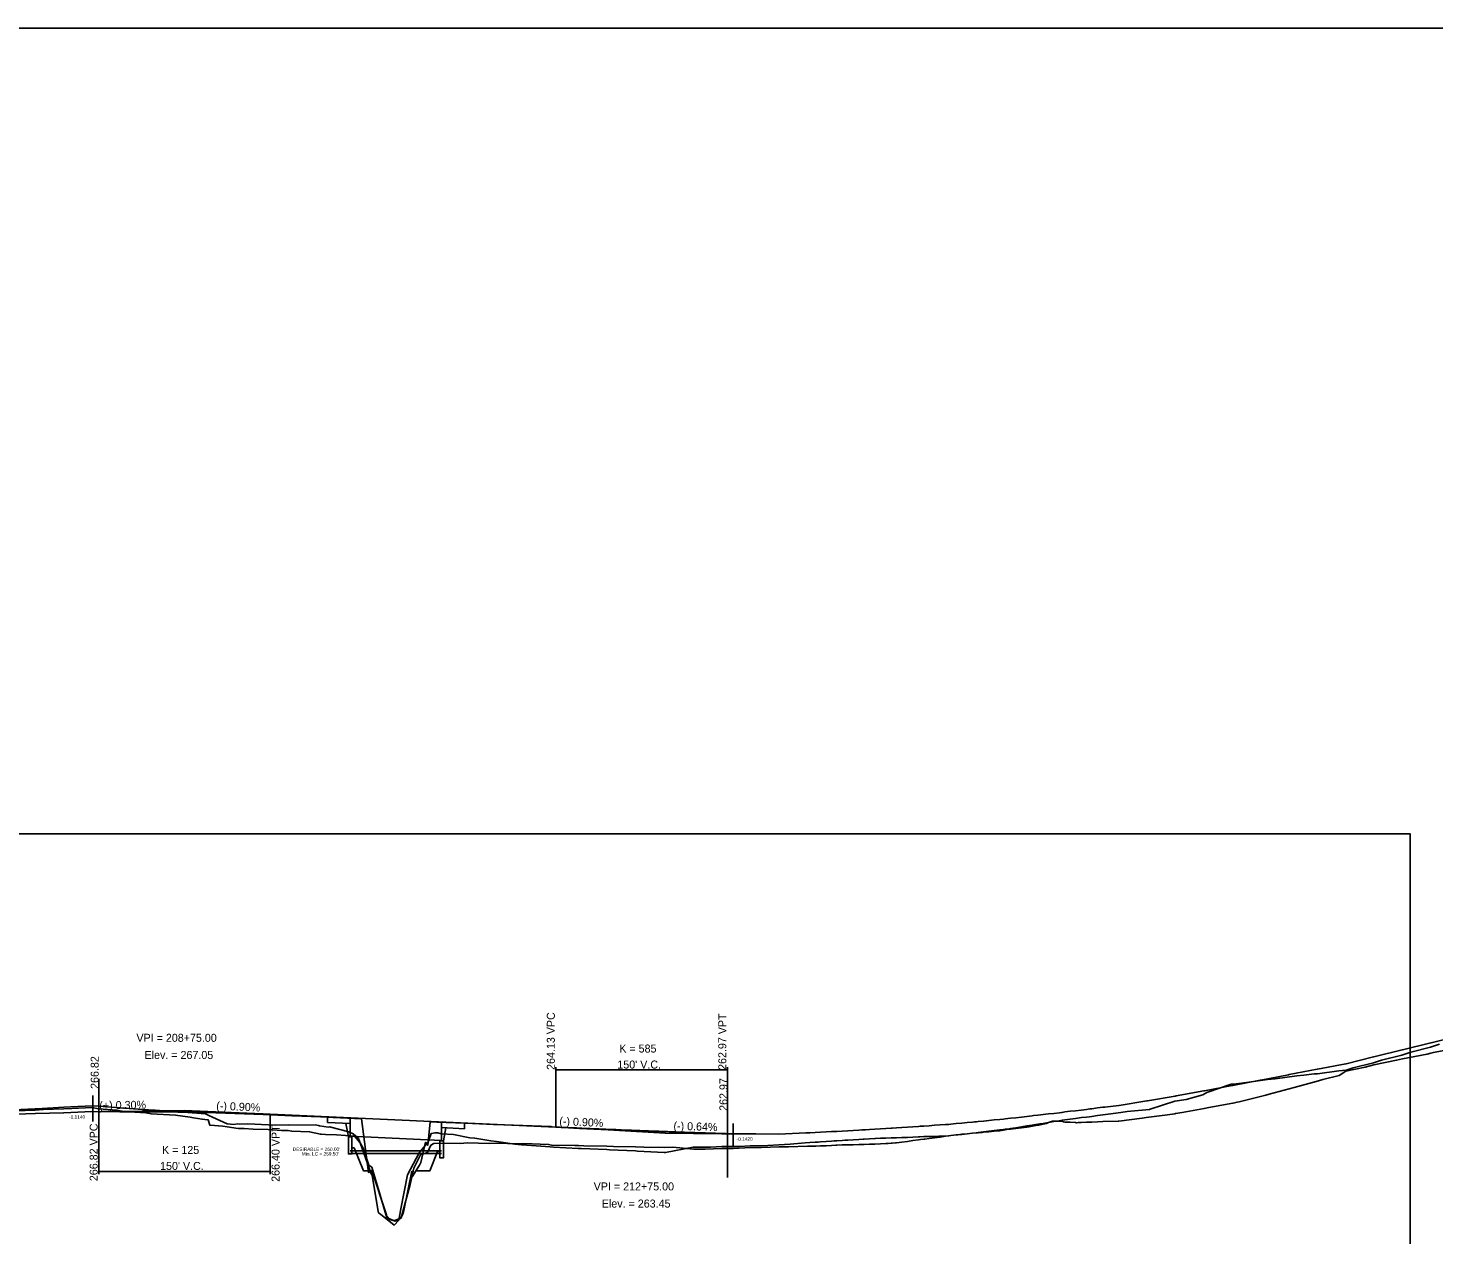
# Model space of a CAD drawing. Extents: x 2018315 to 2021915, y 966584 to 968784.
# Drawn here: x 2019848 to 2021078, y 967728 to 968784 of the extents above; entities that cross this region are included whole.
import ezdxf

# ---------------------------------------------------------------- set-up
doc = ezdxf.new("R2010")
doc.units = 0
for name, color, linetype in [('BR_CONCRETE', 7, 'Continuous'), ('BR_EXIST_GROUND_LT', 7, 'Continuous'), ('BR_EXIST_GROUND_RT', 7, 'Continuous'), ('BR_USER NOTES', 7, 'Continuous'), ('RD_DDB_GradeTX', 7, 'Continuous'), ('RD_DDB_Profile_EX', 7, 'Continuous'), ('RD_DDB_Profile_Lbl', 7, 'Continuous'), ('RD_DDB_Profile_PR', 7, 'Continuous'), ('RD_DDB_StripGrade', 7, 'Continuous'), ('RD_DDB_VCLbl', 7, 'Continuous'), ('RD_SHT_IplotShp', 7, 'Continuous'), ('RD_SHT_ShtClip', 7, 'Continuous')]:
    doc.layers.add(name, color=color, linetype=linetype)

msp = doc.modelspace()

# ---------------------------------------------------------------- linework, layer by layer
at = {"layer": 'BR_CONCRETE'}
for p, q in [((2020109.9, 967831.7), (2020109.9, 967826.7)), ((2020109.9, 967826.7), (2020129.9, 967825.8)), ((2020128.4, 967814.4), (2020126.1, 967826)), ((2020129.9, 967830.9), (2020129.9, 967814.8)), ((2020209.9, 967827.3), (2020209.9, 967811.2)), ((2020209.9, 967822.3), (2020229.9, 967821.4)), ((2020211.4, 967810.8), (2020213.6, 967822.1)), ((2020229.9, 967826.4), (2020229.9, 967821.4)), ((2020129.9, 967814.4), (2020129.9, 967814.8)), ((2020129.9, 967814.8), (2020209.9, 967811.2)), ((2020209.9, 967810.8), (2020209.9, 967811.2)), ((2020131.4, 967804.7), (2020133.4, 967804.7)), ((2020208.4, 967801.3), (2020206.4, 967801.3))]:
    msp.add_line(p, q, dxfattribs=at)
for points in [[(2020128.4, 967814.4), (2020131.4, 967814.4), (2020131.4, 967799.4), (2020128.4, 967799.4)], [(2020211.4, 967810.8), (2020208.4, 967810.8), (2020208.4, 967795.8), (2020211.4, 967795.8)]]:
    msp.add_lwpolyline(points, close=True, dxfattribs=at)
for points in [[(2020133.4, 967804.7), (2020141.4, 967784.6), (2020145.7, 967784.6)], [(2020206.4, 967801.3), (2020199.7, 967784.6), (2020187.6, 967784.6)]]:
    msp.add_lwpolyline(points, dxfattribs=at)
at = {"layer": 'BR_EXIST_GROUND_LT'}
msp.add_lwpolyline([(2019835.5, 967837.8), (2019854.4, 967838.7), (2019860.3, 967839.1), (2019879.4, 967840.1), (2019885.1, 967840.5), (2019904.4, 967841.4), (2019910.3, 967841.1), (2019928.4, 967839.7), (2019948.5, 967838.2), (2019953.4, 967837.9), (2019959.2, 967837.6), (2019978.4, 967836.2), (2019984, 967835.9), (2020003.4, 967834.4), (2020005.7, 967833.3), (2020006.2, 967832.9), (2020022.4, 967825.5), (2020028.2, 967825.1), (2020031.2, 967825.5), (2020033.4, 967825.4), (2020040.4, 967825.5), (2020058.3, 967824.8), (2020064.9, 967824.6), (2020075.7, 967824.7), (2020077.1, 967824.4), (2020099.4, 967824.7), (2020102.1, 967824.1), (2020103.1, 967823.9), (2020110.6, 967822.8), (2020112.1, 967823.1), (2020113, 967822.8), (2020128.8, 967818.6), (2020132.5, 967816.8), (2020137.1, 967812.8), (2020140.2, 967805), (2020148.1, 967781.9), (2020149.1, 967780.8), (2020154.2, 967750.8), (2020154.7, 967747.7), (2020156.3, 967746.5), (2020168.5, 967737.1), (2020172.5, 967741.4), (2020174.1, 967751.2), (2020180, 967781), (2020190.3, 967800.2), (2020195.8, 967807.1), (2020197.5, 967808.2), (2020200.8, 967817.2), (2020204.2, 967817.9), (2020206.6, 967817.7), (2020209.5, 967817), (2020220.4, 967816.3), (2020234.5, 967813.5), (2020238.9, 967813), (2020252.8, 967810.9), (2020258, 967810.3), (2020273.8, 967807.8), (2020279.7, 967807.3), (2020280.3, 967807.3), (2020304.7, 967805.4), (2020307.6, 967805.3), (2020329.4, 967804.2), (2020332, 967804.2), (2020354.4, 967803.1), (2020356.6, 967803), (2020379.4, 967801.9), (2020381.2, 967801.8), (2020404.5, 967800.6), (2020405.7, 967800.7), (2020429.9, 967805.2), (2020445.1, 967805.3), (2020454.9, 967805.9), (2020470.1, 967805.9), (2020479.9, 967806.5), (2020495.2, 967806.6), (2020504.9, 967807.2), (2020514.7, 967807.9), (2020528, 967808.9), (2020532, 967809.2), (2020536.7, 967809.5), (2020539.2, 967809.7), (2020541.4, 967809.8), (2020546.2, 967810.2), (2020550.9, 967810.6), (2020553.3, 967810.7), (2020555.7, 967810.9), (2020560.4, 967811.2), (2020562.9, 967811.4), (2020565.2, 967811.5), (2020569.9, 967811.7), (2020574.7, 967812), (2020578.5, 967812.1), (2020579.4, 967812.2), (2020584.2, 967812.5), (2020588.9, 967812.8), (2020589.3, 967812.8), (2020593.7, 967813), (2020598.4, 967813.1), (2020603.2, 967813.3), (2020603.7, 967813.3), (2020607.9, 967813.5), (2020612.6, 967813.6), (2020616.8, 967813.8), (2020617.4, 967813.8), (2020622.1, 967814.1), (2020626.9, 967814.4), (2020628.2, 967814.4), (2020631.6, 967814.5), (2020636.4, 967814.6), (2020641.1, 967814.7), (2020644.7, 967814.8), (2020645.9, 967814.8), (2020650.6, 967815), (2020653.3, 967815.2), (2020655.4, 967815.4), (2020660.1, 967816), (2020661.5, 967816.1), (2020664.9, 967816.5), (2020669.6, 967816.9), (2020674.4, 967817.4), (2020677.5, 967817.7), (2020679.1, 967817.8), (2020682.7, 967818.2), (2020683.8, 967818.3), (2020688.6, 967818.7), (2020693.3, 967819.1), (2020697.4, 967819.4), (2020698.1, 967819.5), (2020702.8, 967820.5), (2020706, 967820.9), (2020706.8, 967821), (2020707.6, 967821.1), (2020712.3, 967821.7), (2020717.1, 967822.2), (2020721.8, 967822.8), (2020723.9, 967823.1), (2020726.6, 967823.6), (2020731.3, 967824.5), (2020732.3, 967824.6), (2020736.1, 967825.4), (2020739, 967826), (2020740.8, 967826.7), (2020744.4, 967828), (2020745.5, 967828), (2020750.3, 967828.1), (2020752.5, 967828.1), (2020753.9, 967827.3), (2020755, 967827.2), (2020759.8, 967827), (2020764.5, 967826.7), (2020765.2, 967826.6), (2020766.8, 967826.7), (2020769.3, 967826.8), (2020774, 967827), (2020777.1, 967827.2), (2020778.8, 967827.2), (2020783.5, 967827.4), (2020788.3, 967827.6), (2020801.7, 967828), (2020802.2, 967828.1), (2020822.6, 967830.6), (2020826.2, 967831.1), (2020845, 967833.5), (2020851.2, 967834.5), (2020851.9, 967834.6), (2020857.8, 967835.7), (2020876.9, 967839.1), (2020881.1, 967839.9), (2020901.9, 967843.7), (2020902.2, 967843.7), (2020905.7, 967844.6), (2020907.5, 967844.9), (2020930.9, 967850.8), (2020933.7, 967851.5), (2020951.3, 967856.3), (2020955.8, 967857.5), (2020975, 967862.8), (2020980.8, 967864.4), (2020994.9, 967868), (2021000.9, 967871.8), (2021017.9, 967875.1), (2021025.3, 967877.3), (2021045.3, 967881.2), (2021050.3, 967882.5), (2021071.9, 967886.7), (2021075.2, 967887.5), (2021077.5, 967888.1), (2021100.3, 967892.4)], dxfattribs=at)
at = {"layer": 'BR_EXIST_GROUND_RT'}
msp.add_lwpolyline([(2019836.7, 967837), (2019854.3, 967837.6), (2019861.6, 967838.1), (2019879.3, 967838.7), (2019886.4, 967839.2), (2019904.3, 967839.8), (2019909.7, 967838.7), (2019925.9, 967837.6), (2019931.9, 967836.4), (2019951.1, 967835.2), (2019955.9, 967834.3), (2019977, 967833.3), (2019989.8, 967831.6), (2019992.8, 967831), (2020000.3, 967829.6), (2020005, 967829.2), (2020005.7, 967829.1), (2020007.1, 967824.4), (2020007.5, 967824.4), (2020018.6, 967823.5), (2020032, 967821.6), (2020037, 967821.5), (2020045.1, 967820.9), (2020058.1, 967820.6), (2020069.9, 967819.9), (2020075.6, 967819.8), (2020078.8, 967819.1), (2020094.3, 967818.7), (2020103.8, 967816.5), (2020104.4, 967816.5), (2020108.4, 967816.2), (2020117.8, 967816), (2020133.6, 967814.8), (2020138.6, 967809.1), (2020141.2, 967804.3), (2020146.1, 967789.6), (2020148.7, 967787.7), (2020156.2, 967763.3), (2020162, 967743.5), (2020163.6, 967742.7), (2020167.7, 967741.2), (2020170.3, 967741.8), (2020174.5, 967743.4), (2020182.3, 967772.7), (2020185.5, 967786.8), (2020191.3, 967798.4), (2020197.4, 967800.7), (2020200.3, 967806.9), (2020203.2, 967808.4), (2020207.8, 967808.7), (2020226.1, 967808.4), (2020232.5, 967808.9), (2020251.9, 967808.4), (2020257.2, 967808.8), (2020277.7, 967808.2), (2020281.9, 967808.5), (2020303.5, 967807.7), (2020306.1, 967807.1), (2020326.4, 967806.7), (2020329.5, 967806.6), (2020334.3, 967806.5), (2020354.5, 967806), (2020360.3, 967805.9), (2020379.5, 967805.5), (2020386.7, 967805.2), (2020404.7, 967804.8), (2020412.2, 967805.1), (2020430.1, 967803.5), (2020440.4, 967803.5), (2020455.1, 967804.1), (2020464.9, 967804.1), (2020480.1, 967804.8), (2020489.4, 967804.8), (2020505.1, 967805.5), (2020513.4, 967805.5), (2020529.9, 967806.1), (2020532, 967806.1), (2020536.7, 967806.1), (2020537.2, 967806.1), (2020541.4, 967806.3), (2020546.2, 967806.5), (2020550.9, 967806.7), (2020554.8, 967806.9), (2020555.7, 967806.9), (2020560.4, 967807.2), (2020561.2, 967807.2), (2020565.2, 967807.3), (2020569.9, 967807.4), (2020574.7, 967807.5), (2020578.4, 967807.7), (2020579.4, 967807.7), (2020584.2, 967807.8), (2020588.9, 967808), (2020593.7, 967808.2), (2020598.4, 967808.4), (2020600.5, 967808.5), (2020603.2, 967808.7), (2020604.1, 967808.8), (2020606.8, 967809), (2020607.9, 967809.1), (2020612.6, 967809.7), (2020617.4, 967810.3), (2020622.1, 967811), (2020626.9, 967811.6), (2020628.9, 967811.9), (2020631.6, 967812.1), (2020632.5, 967812.2), (2020636.4, 967812.7), (2020641.1, 967813.4), (2020645.9, 967814.1), (2020650.6, 967814.8), (2020653.7, 967815.2), (2020655.4, 967815.4), (2020660.1, 967815.9), (2020664.9, 967816.4), (2020669.6, 967816.9), (2020674.4, 967817.5), (2020678, 967817.9), (2020679.1, 967818), (2020683.8, 967818.6), (2020688.6, 967819.1), (2020693.3, 967819.7), (2020698.1, 967820.3), (2020699.6, 967820.5), (2020702.8, 967820.9), (2020703.2, 967820.9), (2020706.4, 967821.3), (2020707.6, 967821.5), (2020712.3, 967822.2), (2020717.1, 967823), (2020721.8, 967823.8), (2020726.6, 967824.6), (2020728, 967824.9), (2020731.3, 967825.3), (2020733.3, 967825.5), (2020736.1, 967826), (2020740.8, 967826.8), (2020745.5, 967827.6), (2020750.3, 967828.4), (2020752.8, 967828.8), (2020755, 967829.1), (2020759.8, 967829.8), (2020764.5, 967830.4), (2020769.5, 967831.1), (2020774, 967831.6), (2020776.7, 967831.8), (2020778.8, 967832.1), (2020783.5, 967832.8), (2020788.3, 967833.5), (2020795.4, 967834.5), (2020801.6, 967835.4), (2020803.9, 967835.6), (2020809.7, 967836.5), (2020829.2, 967838.3), (2020829.8, 967838.4), (2020851.2, 967845.4), (2020861.1, 967847), (2020875.8, 967851), (2020879.3, 967853.1), (2020900.6, 967860.3), (2020905, 967860.7), (2020914.1, 967861.9), (2020932.3, 967864.4), (2020939.1, 967865), (2020957.9, 967867.6), (2020964.1, 967868.1), (2020973.1, 967869.3), (2020976.2, 967869.5), (2020994.6, 967872.1), (2021001.2, 967872.5), (2021007.4, 967874.5), (2021025, 967878.9), (2021032.2, 967881.3), (2021049.9, 967885.8), (2021057.6, 967888.3), (2021074.9, 967892.7), (2021082.9, 967895.4)], dxfattribs=at)
at = {"layer": 'BR_USER NOTES'}
for p, q in [((2019909.9, 967865.1), (2019909.9, 967819.4)), ((2019904.9, 967850.5), (2019904.9, 967827.6)), ((2020459.9, 967857), (2020459.9, 967778.6)), ((2019904.9, 967836.3), (2019909.9, 967836.2)), ((2020464.9, 967825.8), (2020464.9, 967805.8)), ((2020459.9, 967817), (2020464.9, 967817)), ((2020129.9, 967802.1), (2020209.9, 967802.1)), ((2020129.9, 967799.6), (2020209.9, 967799.6))]:
    msp.add_line(p, q, dxfattribs=at)
at = {"layer": 'RD_DDB_GradeTX'}
for p, q in [((2019909.9, 967836.2), (2019984.9, 967837.4)), ((2020059.9, 967834), (2019984.9, 967837.4)), ((2020304.9, 967823), (2020384.9, 967819.4)), ((2020459.9, 967817), (2020384.9, 967819.4))]:
    msp.add_line(p, q, dxfattribs=at)
at = {"layer": 'RD_DDB_Profile_EX'}
msp.add_lwpolyline([(2019829.5, 967833.7), (2019854.2, 967834.6), (2019854.5, 967834.6), (2019879.1, 967835.4), (2019879.5, 967835.4), (2019904, 967836.3), (2019904.5, 967836.3), (2019928.5, 967836.1), (2019929, 967836.1), (2019929.4, 967836.1), (2019954, 967836), (2019954.4, 967836), (2019979, 967835.8), (2019979.4, 967835.8), (2020004, 967835.7), (2020004.3, 967835.7), (2020028.9, 967834.7), (2020029.3, 967834.7), (2020053.9, 967833.7), (2020054.3, 967833.7), (2020078.9, 967832.7), (2020079.4, 967832.7), (2020103.9, 967831.7), (2020104.2, 967831.7), (2020114.9, 967831.2), (2020115.4, 967831.2), (2020139.8, 967830), (2020145.9, 967783.1), (2020148.9, 967784.8), (2020161.6, 967746.1), (2020162, 967744.9), (2020164.1, 967742.2), (2020164.5, 967742), (2020169.1, 967740.6), (2020173.1, 967742.6), (2020173.8, 967742.9), (2020176.2, 967747.3), (2020176.8, 967749.7), (2020183.9, 967784.1), (2020184.2, 967779.3), (2020190.6, 967789.4), (2020191.7, 967791.8), (2020195.8, 967809.5), (2020197.7, 967806.9), (2020198.6, 967815.5), (2020199.8, 967827.4), (2020205.8, 967827.1), (2020230.1, 967826.2), (2020230.8, 967826.1), (2020255.3, 967825.2), (2020255.7, 967825.1), (2020256.1, 967825.1), (2020280.9, 967824.2), (2020305.4, 967823.2), (2020306.3, 967823.1), (2020330.4, 967821.7), (2020355.5, 967820.3), (2020380.3, 967818.8), (2020380.6, 967818.8), (2020405.3, 967817.4), (2020405.7, 967817.4), (2020430.1, 967817.2), (2020455, 967817), (2020479.8, 967816.9), (2020484.8, 967816.8), (2020504.8, 967816.7), (2020528.4, 967817.8), (2020529.1, 967817.8), (2020532, 967817.9), (2020536.7, 967818.1), (2020541.4, 967818.4), (2020546.2, 967818.6), (2020550.9, 967818.8), (2020552.9, 967818.9), (2020554.1, 967818.9), (2020555.7, 967819), (2020560.4, 967819.3), (2020565.2, 967819.6), (2020569.9, 967819.9), (2020574.7, 967820.1), (2020577.4, 967820.3), (2020579, 967820.4), (2020579.4, 967820.4), (2020580.6, 967820.5), (2020584.2, 967820.7), (2020588.9, 967821), (2020593.7, 967821.2), (2020598.4, 967821.5), (2020603.2, 967821.8), (2020604, 967821.8), (2020607.9, 967822.1), (2020612.6, 967822.4), (2020617.4, 967822.7), (2020622.1, 967823.1), (2020626.9, 967823.4), (2020628.6, 967823.5), (2020631.6, 967823.7), (2020636.4, 967824), (2020641.1, 967824.4), (2020645.9, 967824.7), (2020650.6, 967825), (2020651.9, 967825.1), (2020653.6, 967825.2), (2020655.4, 967825.4), (2020660.1, 967825.8), (2020664.9, 967826.3), (2020669.6, 967826.7), (2020674.4, 967827.2), (2020676.1, 967827.4), (2020677.8, 967827.5), (2020679.1, 967827.6), (2020683.8, 967828.1), (2020688.6, 967828.5), (2020693.3, 967829), (2020698.1, 967829.4), (2020701.4, 967829.8), (2020702.8, 967829.9), (2020707.6, 967830.5), (2020712.3, 967831), (2020717.1, 967831.6), (2020721.8, 967832.1), (2020726.6, 967832.7), (2020727.7, 967832.8), (2020731.3, 967833.2), (2020736.1, 967833.8), (2020740.8, 967834.3), (2020745.5, 967834.8), (2020750.3, 967835.4), (2020752, 967835.6), (2020752.7, 967835.7), (2020755, 967836), (2020759.8, 967836.6), (2020764.5, 967837.1), (2020769.3, 967837.7), (2020774, 967838.3), (2020777, 967838.7), (2020777.3, 967838.7), (2020778.8, 967838.9), (2020783.5, 967839.5), (2020788.3, 967840.1), (2020790.1, 967840.3), (2020802.3, 967841.8), (2020802.6, 967841.8), (2020826.7, 967845.7), (2020827.3, 967845.9), (2020851.7, 967849.8), (2020852.5, 967850), (2020876.5, 967854.5), (2020877.3, 967854.6), (2020901.5, 967859.2), (2020902.1, 967859.3), (2020925.9, 967863.8), (2020926.4, 967863.9), (2020950.8, 967868.6), (2020951.3, 967868.7), (2020975.8, 967873.4), (2020976.2, 967873.5), (2021000.8, 967878.1), (2021001.1, 967878.2), (2021025.1, 967884.2), (2021025.5, 967884.3), (2021050.1, 967890.3), (2021050.5, 967890.4), (2021075.1, 967896.5), (2021075.5, 967896.6), (2021100, 967902.7)], dxfattribs=at)
at = {"layer": 'RD_DDB_Profile_PR'}
msp.add_line((2020059.9, 967834), (2020309.9, 967822.8), dxfattribs=at)
for points in [[(2019909.9, 967836.2), (2019912.9, 967836.3), (2019915.9, 967836.3), (2019918.9, 967836.4), (2019921.9, 967836.4), (2019924.9, 967836.4), (2019927.9, 967836.4), (2019930.9, 967836.5), (2019933.9, 967836.5), (2019936.9, 967836.5), (2019939.9, 967836.5), (2019942.9, 967836.5), (2019945.9, 967836.5), (2019948.9, 967836.5), (2019951.9, 967836.5), (2019954.9, 967836.5), (2019957.9, 967836.5), (2019960.9, 967836.5), (2019963.9, 967836.5), (2019966.9, 967836.4), (2019969.9, 967836.4), (2019972.9, 967836.4), (2019975.9, 967836.4), (2019978.9, 967836.3), (2019981.9, 967836.3), (2019984.9, 967836.2), (2019987.9, 967836.2), (2019990.9, 967836.1), (2019993.9, 967836.1), (2019996.9, 967836), (2019999.9, 967836), (2020002.9, 967835.9), (2020005.9, 967835.8), (2020008.9, 967835.8), (2020011.9, 967835.7), (2020014.9, 967835.6), (2020017.9, 967835.5), (2020020.9, 967835.4), (2020023.9, 967835.4), (2020026.9, 967835.3), (2020029.9, 967835.2), (2020032.9, 967835.1), (2020035.9, 967835), (2020038.9, 967834.9), (2020041.9, 967834.7), (2020044.9, 967834.6), (2020047.9, 967834.5), (2020050.9, 967834.4), (2020053.9, 967834.3), (2020056.9, 967834.1), (2020059.9, 967834)], [(2020309.9, 967822.8), (2020312.9, 967822.6), (2020315.9, 967822.5), (2020318.9, 967822.4), (2020321.9, 967822.2), (2020324.9, 967822.1), (2020327.9, 967822), (2020330.9, 967821.8), (2020333.9, 967821.7), (2020336.9, 967821.6), (2020339.9, 967821.5), (2020342.9, 967821.3), (2020345.9, 967821.2), (2020348.9, 967821.1), (2020351.9, 967821), (2020354.9, 967820.8), (2020357.9, 967820.7), (2020360.9, 967820.6), (2020363.9, 967820.5), (2020366.9, 967820.3), (2020369.9, 967820.2), (2020372.9, 967820.1), (2020375.9, 967820), (2020378.9, 967819.9), (2020381.9, 967819.8), (2020384.9, 967819.6), (2020387.9, 967819.5), (2020390.9, 967819.4), (2020393.9, 967819.3), (2020396.9, 967819.2), (2020399.9, 967819.1), (2020402.9, 967819), (2020405.9, 967818.9), (2020408.9, 967818.7), (2020411.9, 967818.6), (2020414.9, 967818.5), (2020417.9, 967818.4), (2020420.9, 967818.3), (2020423.9, 967818.2), (2020426.9, 967818.1), (2020429.9, 967818), (2020432.9, 967817.9), (2020435.9, 967817.8), (2020438.9, 967817.7), (2020441.9, 967817.6), (2020444.9, 967817.5), (2020447.9, 967817.4), (2020450.9, 967817.3), (2020453.9, 967817.2), (2020456.9, 967817.1), (2020459.9, 967817)]]:
    msp.add_spline(points, degree=3, dxfattribs=at)
at = {"layer": 'RD_DDB_VCLbl'}
for p, q in [((2020309.9, 967875.3), (2020309.9, 967822.8)), ((2020309.9, 967872.8), (2020459.9, 967872.8)), ((2020459.9, 967875.3), (2020459.9, 967817)), ((2019909.9, 967781.5), (2019909.9, 967836.2)), ((2020059.9, 967781.5), (2020059.9, 967834)), ((2019909.9, 967784), (2020059.9, 967784))]:
    msp.add_line(p, q, dxfattribs=at)
at = {"layer": 'RD_SHT_IplotShp'}
msp.add_lwpolyline([(2018314.5, 966584.2), (2021914.5, 966584.2), (2021914.5, 968784.2), (2018314.5, 968784.2)], close=True, dxfattribs=at)
at = {"layer": 'RD_SHT_ShtClip'}
msp.add_lwpolyline([(2019257.2, 968079.2), (2021057.2, 968079.2), (2021057.2, 966979.2), (2019257.2, 966979.2)], close=True, dxfattribs=at)

# ---------------------------------------------------------------- texts
at = {"layer": 'BR_USER NOTES'}
for s, p in [('-0.1140', (2019884, 967830.2)), ('-0.1420', (2020467.9, 967810.8)), ("DESIRABLE = 260.00'", (2020079.6, 967801.9)), ("Min. LC = 259.50'", (2020087.6, 967797.9))]:
    msp.add_text(s, height=3, dxfattribs=at).set_placement(p)
at = {"layer": 'RD_DDB_GradeTX'}
for s, rotation, p in [('(+) 0.30%', 0.8594, (2019910.5, 967838.3)), ('(-) 0.90%', 357.4282, (2020012.6, 967838.1)), ('(-) 0.90%', 357.4282, (2020312.7, 967824.6)), ('(-) 0.64%', 358.1614, (2020412.6, 967820.5))]:
    msp.add_text(s, height=7, rotation=rotation, dxfattribs=at).set_placement(p)
at = {"layer": 'RD_DDB_Profile_Lbl'}
for s, p in [('VPI = 208+75.00', (2019942.9, 967897.4)), ('Elev. = 267.05', (2019950, 967882.4)), ('VPI = 212+75.00', (2020342.9, 967767.4)), ('Elev. = 263.45', (2020350, 967752.4))]:
    msp.add_text(s, height=7, dxfattribs=at).set_placement(p)
for s, p in [('266.82', (2019909.9, 967856.2)), ('262.97', (2020459.9, 967837))]:
    msp.add_text(s, height=7, rotation=90, dxfattribs=at).set_placement(p)
at = {"layer": 'RD_DDB_StripGrade'}
for s, p in [('264.13 VPC', (2020308.9, 967872.8)), ('262.97 VPT', (2020458.9, 967872.8)), ('266.82 VPC', (2019909, 967775.5)), ('266.40 VPT', (2020068.1, 967774.9))]:
    msp.add_text(s, height=7, rotation=90, dxfattribs=at).set_placement(p)
at = {"layer": 'RD_DDB_VCLbl'}
for s, p in [('K = 585', (2020365.3, 967888)), ("150' V.C.", (2020363.6, 967874)), ('K = 125', (2019965.3, 967799.3)), ("150' V.C.", (2019963.6, 967785.3))]:
    msp.add_text(s, height=7, dxfattribs=at).set_placement(p)

doc.saveas('drawing.dxf')
